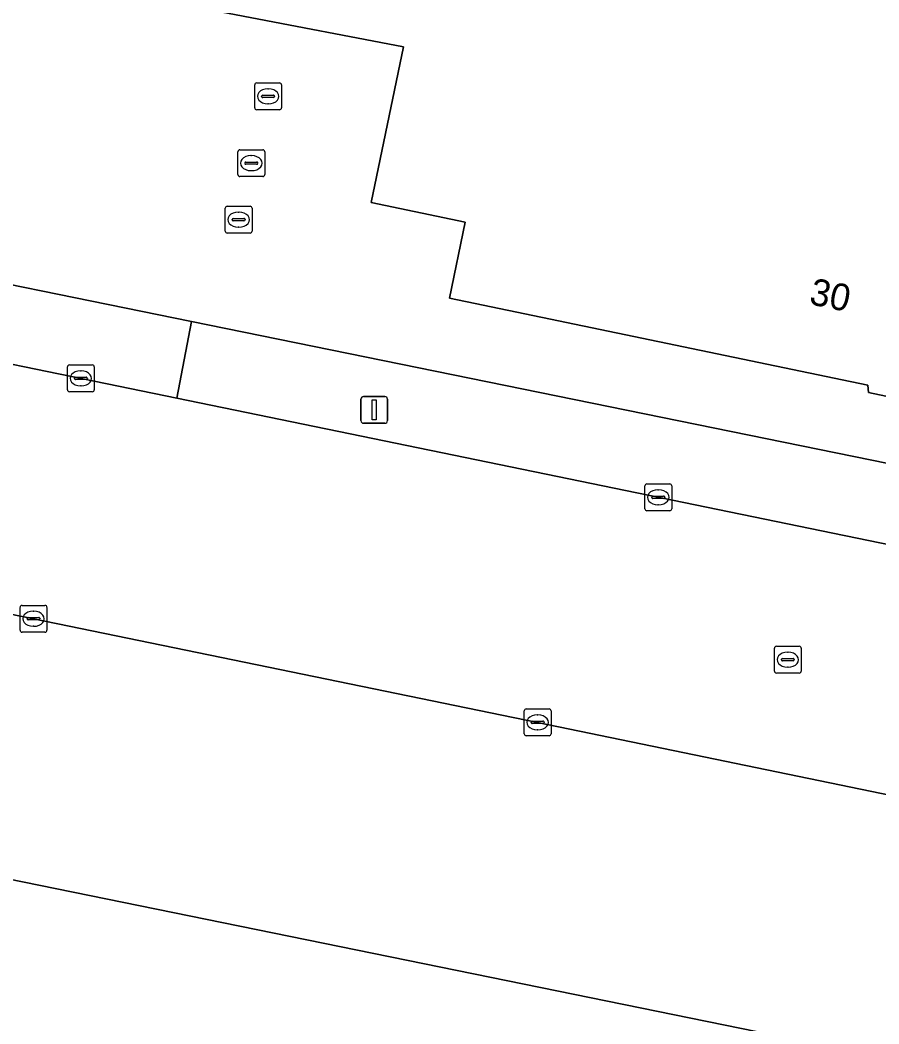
# Model space of a CAD drawing. Extents: x 157692 to 159674, y 381452 to 383291.
# Drawn here: x 158645.42 to 158677.43, y 382302.74 to 382340.17 of the extents above; entities that cross this region are included whole.
import ezdxf

# ---------------------------------------------------------------- set-up
doc = ezdxf.new("R2010")
doc.units = 0
for name, color, linetype in [('IMGEO_Erf', 7, 'Continuous'), ('IMGEO_Kolk', 7, 'Continuous'), ('IMGEO_Lichtmast', 7, 'Continuous'), ('IMGEO_Pand', 7, 'Continuous'), ('IMGEO_Pand_nummerreeks', 7, 'Continuous'), ('IMGEO_Rijbaan_lokaal_open', 7, 'Continuous'), ('IMGEO_Rioolput', 7, 'Continuous'), ('IMGEO_Voetpad_open', 7, 'Continuous')]:
    doc.layers.add(name, color=color, linetype=linetype)

msp = doc.modelspace()

# ---------------------------------------------------------------- linework, layer by layer
at = {"layer": 'IMGEO_Erf'}
for points in [[(158587.674, 382342.018), (158618.492, 382335.729), (158631.037, 382333.169), (158639.982, 382331.344), (158651.812, 382328.93), (158690.748, 382320.985), (158691.802, 382326.896), (158689.423, 382327.389), (158688.864, 382324.687), (158680.463, 382326.427), (158680.047, 382325.647), (158677.033, 382326.278), (158677.008, 382326.55), (158661.422, 382329.799), (158662.011, 382332.639), (158658.506, 382333.365), (158659.707, 382339.164), (158647.763, 382341.465)], [(158774.915, 382281.626), (158583.923, 382320.599), (158578.836, 382321.712), (158578.49, 382320.049), (158577.977, 382317.433), (158573.17, 382294.226), (158571.648, 382286.878), (158568.676, 382272.426), (158569.594, 382272.252), (158568.934, 382269.03), (158568.022, 382269.232), (158563.842, 382248.283), (158559.221, 382225.883), (158556.642, 382213.448), (158553.461, 382197.47)]]:
    msp.add_lwpolyline(points, dxfattribs=at)
at = {"layer": 'IMGEO_Kolk'}
for p, q in [((158647.182, 382326.383), (158647.182, 382327.235)), ((158647.257, 382327.309), (158648.109, 382327.309)), ((158647.67, 382327.089), (158647.695, 382327.089)), ((158648.183, 382327.235), (158648.183, 382326.383)), ((158647.441, 382326.803), (158647.441, 382326.815)), ((158647.879, 382326.766), (158647.481, 382326.766)), ((158647.484, 382326.852), (158647.882, 382326.852)), ((158647.925, 382326.815), (158647.925, 382326.803)), ((158648.109, 382326.309), (158647.257, 382326.309)), ((158647.693, 382326.529), (158647.668, 382326.529)), ((158668.704, 382321.949), (158668.704, 382322.801)), ((158668.779, 382322.875), (158669.631, 382322.875)), ((158669.192, 382322.655), (158669.217, 382322.655)), ((158669.705, 382322.801), (158669.705, 382321.949)), ((158668.963, 382322.369), (158668.963, 382322.381)), ((158669.401, 382322.332), (158669.003, 382322.332)), ((158669.006, 382322.418), (158669.404, 382322.418)), ((158669.447, 382322.381), (158669.447, 382322.369)), ((158669.631, 382321.875), (158668.779, 382321.875)), ((158669.215, 382322.095), (158669.19, 382322.095)), ((158645.418, 382317.421), (158645.418, 382318.273)), ((158645.493, 382318.347), (158646.345, 382318.347)), ((158645.906, 382318.127), (158645.931, 382318.127)), ((158646.419, 382318.273), (158646.419, 382317.421)), ((158645.677, 382317.841), (158645.677, 382317.853)), ((158646.115, 382317.804), (158645.717, 382317.804)), ((158645.72, 382317.89), (158646.118, 382317.89)), ((158646.161, 382317.853), (158646.161, 382317.841)), ((158646.345, 382317.347), (158645.493, 382317.347)), ((158645.929, 382317.567), (158645.904, 382317.567)), ((158664.206, 382313.558), (158664.206, 382314.41)), ((158664.281, 382314.484), (158665.133, 382314.484)), ((158665.207, 382314.41), (158665.207, 382313.558)), ((158664.465, 382313.978), (158664.465, 382313.99)), ((158664.903, 382313.941), (158664.505, 382313.941)), ((158664.508, 382314.027), (158664.906, 382314.027)), ((158664.694, 382314.264), (158664.719, 382314.264)), ((158664.949, 382313.99), (158664.949, 382313.978)), ((158664.717, 382313.704), (158664.692, 382313.704)), ((158665.133, 382313.484), (158664.281, 382313.484))]:
    msp.add_line(p, q, dxfattribs=at)
for points in [[(158647.182, 382326.383), (158647.182, 382327.235)], [(158647.257, 382327.309), (158648.109, 382327.309)], [(158648.183, 382327.235), (158648.183, 382326.383)], [(158648.109, 382326.309), (158647.257, 382326.309)], [(158668.704, 382321.949), (158668.704, 382322.801)], [(158668.779, 382322.875), (158669.631, 382322.875)], [(158669.705, 382322.801), (158669.705, 382321.949)], [(158669.631, 382321.875), (158668.779, 382321.875)], [(158645.418, 382317.421), (158645.418, 382318.273)], [(158645.493, 382318.347), (158646.345, 382318.347)], [(158646.419, 382318.273), (158646.419, 382317.421)], [(158646.345, 382317.347), (158645.493, 382317.347)], [(158664.206, 382313.558), (158664.206, 382314.41)], [(158664.281, 382314.484), (158665.133, 382314.484)], [(158665.207, 382314.41), (158665.207, 382313.558)], [(158665.133, 382313.484), (158664.281, 382313.484)]]:
    msp.add_lwpolyline(points, dxfattribs=at)
for centre, radius, start, end in [((158647.259, 382327.233), 0.0765, 91.552, 178.448), ((158647.259, 382327.233), 0.0765, 91.552, 178.448), ((158648.107, 382327.233), 0.0765, 1.552, 88.448), ((158648.107, 382327.233), 0.0765, 1.552, 88.448), ((158647.481, 382326.812), 0.0403, 85.8775, 175.7526), ((158647.478, 382326.802), 0.0366, 178.938, 274.7102), ((158647.882, 382326.809), 0.043, 264.8664, 352.4533), ((158647.886, 382326.814), 0.0386, 1.7309, 96.639), ((158647.259, 382326.385), 0.0765, 181.552, 268.448), ((158647.259, 382326.385), 0.0765, 181.552, 268.448), ((158648.107, 382326.385), 0.0765, 271.552, 358.448), ((158648.107, 382326.385), 0.0765, 271.552, 358.448), ((158668.781, 382322.799), 0.0765, 91.552, 178.448), ((158668.781, 382322.799), 0.0765, 91.552, 178.448), ((158669.629, 382322.799), 0.0765, 1.552, 88.448), ((158669.629, 382322.799), 0.0765, 1.552, 88.448), ((158669.003, 382322.378), 0.0403, 85.8775, 175.7526), ((158669, 382322.368), 0.0366, 178.938, 274.7102), ((158669.404, 382322.375), 0.043, 264.8664, 352.4533), ((158669.408, 382322.38), 0.0386, 1.7309, 96.639), ((158668.781, 382321.951), 0.0765, 181.552, 268.448), ((158668.781, 382321.951), 0.0765, 181.552, 268.448), ((158669.629, 382321.951), 0.0765, 271.552, 358.448), ((158669.629, 382321.951), 0.0765, 271.552, 358.448), ((158645.495, 382318.271), 0.0765, 91.552, 178.448), ((158645.495, 382318.271), 0.0765, 91.552, 178.448), ((158646.343, 382318.271), 0.0765, 1.552, 88.448), ((158646.343, 382318.271), 0.0765, 1.552, 88.448), ((158645.717, 382317.85), 0.0403, 85.8775, 175.7526), ((158645.714, 382317.84), 0.0366, 178.938, 274.7102), ((158646.118, 382317.847), 0.043, 264.8664, 352.4533), ((158646.122, 382317.852), 0.0386, 1.7309, 96.639), ((158645.495, 382317.423), 0.0765, 181.552, 268.448), ((158645.495, 382317.423), 0.0765, 181.552, 268.448), ((158646.343, 382317.423), 0.0765, 271.552, 358.448), ((158646.343, 382317.423), 0.0765, 271.552, 358.448), ((158664.283, 382314.408), 0.0765, 91.552, 178.448), ((158664.283, 382314.408), 0.0765, 91.552, 178.448), ((158665.131, 382314.408), 0.0765, 1.552, 88.448), ((158665.131, 382314.408), 0.0765, 1.552, 88.448), ((158664.505, 382313.987), 0.0403, 85.8775, 175.7526), ((158664.502, 382313.977), 0.0366, 178.938, 274.7102), ((158664.906, 382313.984), 0.043, 264.8664, 352.4533), ((158664.91, 382313.989), 0.0386, 1.7309, 96.639), ((158664.283, 382313.56), 0.0765, 181.552, 268.448), ((158664.283, 382313.56), 0.0765, 181.552, 268.448), ((158665.131, 382313.56), 0.0765, 271.552, 358.448), ((158665.131, 382313.56), 0.0765, 271.552, 358.448)]:
    msp.add_arc(centre, radius, start, end, dxfattribs=at)
for centre, major_axis, ratio, start_param, end_param in [((158647.669, 382326.809), (-0.387, 0.002), 0.722429, 4.712389, 7.853982), ((158647.694, 382326.809), (-0.39, 0.002), 0.717154, 1.570796, 4.712389), ((158669.191, 382322.375), (-0.387, 0.002), 0.722429, 4.712389, 7.853982), ((158669.216, 382322.375), (-0.39, 0.002), 0.717154, 1.570796, 4.712389), ((158645.905, 382317.847), (-0.387, 0.002), 0.722429, 4.712389, 7.853982), ((158645.93, 382317.847), (-0.39, 0.002), 0.717154, 1.570796, 4.712389), ((158664.693, 382313.984), (-0.387, 0.002), 0.722429, 4.712389, 7.853982), ((158664.718, 382313.984), (-0.39, 0.002), 0.717154, 1.570796, 4.712389)]:
    msp.add_ellipse(centre, major_axis=major_axis, ratio=ratio, start_param=start_param, end_param=end_param, dxfattribs=at)
at = {"layer": 'IMGEO_Lichtmast'}
for p, q in [((158658.122, 382325.234), (158658.122, 382326.034)), ((158658.122, 382326.034), (158658.122, 382325.234)), ((158658.222, 382326.134), (158659.012, 382326.134)), ((158659.012, 382326.134), (158658.222, 382326.134)), ((158659.112, 382326.034), (158659.112, 382325.234)), ((158659.112, 382325.234), (158659.112, 382326.034)), ((158659.012, 382325.134), (158658.222, 382325.134)), ((158658.222, 382325.134), (158659.012, 382325.134))]:
    msp.add_line(p, q, dxfattribs=at)
msp.add_lwpolyline([(158658.542, 382326.009), (158658.692, 382326.009), (158658.692, 382325.259), (158658.542, 382325.259), (158658.542, 382326.009)], dxfattribs=at)
for centre, start, end in [((158658.222, 382326.034), 90, 180), ((158658.222, 382326.034), 90, 180), ((158659.012, 382326.034), 0, 90), ((158659.012, 382326.034), 360, 90), ((158658.222, 382325.234), 180, 270), ((158658.222, 382325.234), 180, 270), ((158659.012, 382325.234), 270, 0), ((158659.012, 382325.234), 270, 0)]:
    msp.add_arc(centre, 0.1, start, end, dxfattribs=at)
at = {"layer": 'IMGEO_Pand'}
msp.add_lwpolyline([(158655.283, 382370.984), (158642.548, 382373.594), (158636.447, 382343.782), (158647.763, 382341.465), (158659.707, 382339.164), (158658.506, 382333.365), (158662.011, 382332.639), (158661.422, 382329.799), (158677.008, 382326.55), (158677.033, 382326.278), (158680.047, 382325.647), (158680.463, 382326.427), (158688.864, 382324.687), (158689.423, 382327.389), (158691.802, 382326.896), (158695.197, 382343.266), (158690.865, 382344.152), (158691.721, 382348.337), (158696.064, 382347.447), (158699.065, 382362.008)], close=True, dxfattribs=at)
at = {"layer": 'IMGEO_Rijbaan_lokaal_open'}
for points in [[(158744.89, 382306.754), (158742.717, 382307.23), (158723.644, 382311.136), (158714.521, 382313.011), (158712.813, 382313.362), (158711.707, 382313.592), (158693.337, 382317.409), (158651.257, 382326.067), (158639.414, 382328.503), (158630.487, 382330.34), (158617.947, 382332.92), (158590.277, 382338.612), (158586.837, 382339.353), (158586.676, 382339.386), (158584.918, 382330.64)], [(158585.369, 382330.295), (158606.304, 382326.032), (158627.099, 382321.705), (158645.918, 382317.846), (158664.706, 382313.983), (158683.357, 382310.127), (158703.229, 382305.989), (158720.558, 382302.454), (158740.076, 382298.433), (158761.28, 382294.05), (158776.976, 382290.837), (158783.229, 382289.567), (158794.751, 382287.205), (158799.061, 382286.324), (158819.844, 382282.089), (158838.842, 382278.204), (158844.942, 382276.94), (158852.145, 382275.448)]]:
    msp.add_lwpolyline(points, dxfattribs=at)
msp.add_lwpolyline([(158651.257, 382326.067), (158651.812, 382328.93), (158639.982, 382331.344), (158639.414, 382328.503)], close=True, dxfattribs=at)
at = {"layer": 'IMGEO_Rioolput'}
for p, q in [((158654.162, 382336.899), (158654.162, 382337.751)), ((158654.237, 382337.825), (158655.089, 382337.825)), ((158654.65, 382337.605), (158654.675, 382337.605)), ((158655.163, 382337.751), (158655.163, 382336.899)), ((158654.421, 382337.319), (158654.421, 382337.331)), ((158654.859, 382337.282), (158654.461, 382337.282)), ((158654.464, 382337.368), (158654.862, 382337.368)), ((158654.905, 382337.331), (158654.905, 382337.319)), ((158655.089, 382336.825), (158654.237, 382336.825)), ((158654.673, 382337.045), (158654.648, 382337.045)), ((158653.536, 382334.407), (158653.536, 382335.259)), ((158653.611, 382335.333), (158654.463, 382335.333)), ((158654.537, 382335.259), (158654.537, 382334.407)), ((158653.838, 382334.876), (158654.236, 382334.876)), ((158654.024, 382335.113), (158654.049, 382335.113)), ((158653.795, 382334.827), (158653.795, 382334.839)), ((158654.233, 382334.79), (158653.835, 382334.79)), ((158654.047, 382334.553), (158654.022, 382334.553)), ((158654.279, 382334.839), (158654.279, 382334.827)), ((158654.463, 382334.333), (158653.611, 382334.333)), ((158653.064, 382332.3), (158653.064, 382333.152)), ((158653.139, 382333.226), (158653.991, 382333.226)), ((158653.552, 382333.006), (158653.577, 382333.006)), ((158654.065, 382333.152), (158654.065, 382332.3)), ((158653.323, 382332.72), (158653.323, 382332.732)), ((158653.761, 382332.683), (158653.363, 382332.683)), ((158653.366, 382332.769), (158653.764, 382332.769)), ((158653.807, 382332.732), (158653.807, 382332.72)), ((158653.575, 382332.446), (158653.55, 382332.446)), ((158653.991, 382332.226), (158653.139, 382332.226)), ((158673.531, 382315.894), (158673.531, 382316.746)), ((158673.606, 382316.82), (158674.458, 382316.82)), ((158674.019, 382316.6), (158674.044, 382316.6)), ((158674.532, 382316.746), (158674.532, 382315.894)), ((158673.79, 382316.314), (158673.79, 382316.326)), ((158674.228, 382316.277), (158673.83, 382316.277)), ((158673.833, 382316.363), (158674.231, 382316.363)), ((158674.274, 382316.326), (158674.274, 382316.314)), ((158674.458, 382315.82), (158673.606, 382315.82)), ((158674.042, 382316.04), (158674.017, 382316.04))]:
    msp.add_line(p, q, dxfattribs=at)
for points in [[(158654.162, 382336.899), (158654.162, 382337.751)], [(158654.237, 382337.825), (158655.089, 382337.825)], [(158655.163, 382337.751), (158655.163, 382336.899)], [(158655.089, 382336.825), (158654.237, 382336.825)], [(158653.536, 382334.407), (158653.536, 382335.259)], [(158653.611, 382335.333), (158654.463, 382335.333)], [(158654.537, 382335.259), (158654.537, 382334.407)], [(158654.463, 382334.333), (158653.611, 382334.333)], [(158653.064, 382332.3), (158653.064, 382333.152)], [(158653.139, 382333.226), (158653.991, 382333.226)], [(158654.065, 382333.152), (158654.065, 382332.3)], [(158653.991, 382332.226), (158653.139, 382332.226)], [(158673.531, 382315.894), (158673.531, 382316.746)], [(158673.606, 382316.82), (158674.458, 382316.82)], [(158674.532, 382316.746), (158674.532, 382315.894)], [(158674.458, 382315.82), (158673.606, 382315.82)]]:
    msp.add_lwpolyline(points, dxfattribs=at)
for centre, radius, start, end in [((158654.239, 382337.749), 0.0765, 91.552, 178.448), ((158654.239, 382337.749), 0.0765, 91.552, 178.448), ((158655.087, 382337.749), 0.0765, 1.552, 88.448), ((158655.087, 382337.749), 0.0765, 1.552, 88.448), ((158654.461, 382337.328), 0.0403, 85.8775, 175.7526), ((158654.458, 382337.318), 0.0366, 178.938, 274.7102), ((158654.862, 382337.325), 0.043, 264.8664, 352.4533), ((158654.866, 382337.33), 0.0386, 1.7309, 96.639), ((158654.239, 382336.901), 0.0765, 181.552, 268.448), ((158654.239, 382336.901), 0.0765, 181.552, 268.448), ((158655.087, 382336.901), 0.0765, 271.552, 358.448), ((158655.087, 382336.901), 0.0765, 271.552, 358.448), ((158653.613, 382335.257), 0.0765, 91.552, 178.448), ((158653.613, 382335.257), 0.0765, 91.552, 178.448), ((158654.461, 382335.257), 0.0765, 1.552, 88.448), ((158654.461, 382335.257), 0.0765, 1.552, 88.448), ((158653.835, 382334.836), 0.0403, 85.8775, 175.7526), ((158654.24, 382334.838), 0.0386, 1.7309, 96.639), ((158653.832, 382334.826), 0.0366, 178.938, 274.7102), ((158654.236, 382334.833), 0.043, 264.8664, 352.4533), ((158653.613, 382334.409), 0.0765, 181.552, 268.448), ((158653.613, 382334.409), 0.0765, 181.552, 268.448), ((158654.461, 382334.409), 0.0765, 271.552, 358.448), ((158654.461, 382334.409), 0.0765, 271.552, 358.448), ((158653.141, 382333.15), 0.0765, 91.552, 178.448), ((158653.141, 382333.15), 0.0765, 91.552, 178.448), ((158653.989, 382333.15), 0.0765, 1.552, 88.448), ((158653.989, 382333.15), 0.0765, 1.552, 88.448), ((158653.363, 382332.729), 0.0403, 85.8775, 175.7526), ((158653.36, 382332.719), 0.0366, 178.938, 274.7102), ((158653.764, 382332.726), 0.043, 264.8664, 352.4533), ((158653.768, 382332.731), 0.0386, 1.7309, 96.639), ((158653.141, 382332.302), 0.0765, 181.552, 268.448), ((158653.141, 382332.302), 0.0765, 181.552, 268.448), ((158653.989, 382332.302), 0.0765, 271.552, 358.448), ((158653.989, 382332.302), 0.0765, 271.552, 358.448), ((158673.608, 382316.744), 0.0765, 91.552, 178.448), ((158673.608, 382316.744), 0.0765, 91.552, 178.448), ((158674.456, 382316.744), 0.0765, 1.552, 88.448), ((158674.456, 382316.744), 0.0765, 1.552, 88.448), ((158673.83, 382316.323), 0.0403, 85.8775, 175.7526), ((158673.827, 382316.313), 0.0366, 178.938, 274.7102), ((158674.231, 382316.32), 0.043, 264.8664, 352.4533), ((158674.235, 382316.325), 0.0386, 1.7309, 96.639), ((158673.608, 382315.896), 0.0765, 181.552, 268.448), ((158673.608, 382315.896), 0.0765, 181.552, 268.448), ((158674.456, 382315.896), 0.0765, 271.552, 358.448), ((158674.456, 382315.896), 0.0765, 271.552, 358.448)]:
    msp.add_arc(centre, radius, start, end, dxfattribs=at)
for centre, major_axis, ratio, start_param, end_param in [((158654.649, 382337.325), (-0.387, 0.002), 0.722429, 4.712389, 7.853982), ((158654.674, 382337.325), (-0.39, 0.002), 0.717154, 1.570796, 4.712389), ((158654.023, 382334.833), (-0.387, 0.002), 0.722429, 4.712389, 7.853982), ((158654.048, 382334.833), (-0.39, 0.002), 0.717154, 1.570796, 4.712389), ((158653.551, 382332.726), (-0.387, 0.002), 0.722429, 4.712389, 7.853982), ((158653.576, 382332.726), (-0.39, 0.002), 0.717154, 1.570796, 4.712389), ((158674.018, 382316.32), (-0.387, 0.002), 0.722429, 4.712389, 7.853982), ((158674.043, 382316.32), (-0.39, 0.002), 0.717154, 1.570796, 4.712389)]:
    msp.add_ellipse(centre, major_axis=major_axis, ratio=ratio, start_param=start_param, end_param=end_param, dxfattribs=at)
at = {"layer": 'IMGEO_Voetpad_open'}
for points in [[(158776.976, 382290.837), (158761.28, 382294.05), (158740.076, 382298.433), (158720.558, 382302.454), (158703.229, 382305.989), (158683.357, 382310.127), (158664.706, 382313.983), (158645.918, 382317.846), (158627.099, 382321.705), (158606.304, 382326.032), (158585.369, 382330.295)], [(158693.858, 382320.35), (158691.021, 382320.929), (158690.748, 382320.985), (158651.812, 382328.93), (158651.257, 382326.067), (158693.337, 382317.409)], [(158585.636, 382328.823), (158583.923, 382320.599), (158774.915, 382281.626), (158775.174, 382281.573), (158776.28, 382289.179), (158776.115, 382289.213), (158776.367, 382290.437)]]:
    msp.add_lwpolyline(points, dxfattribs=at)

# ---------------------------------------------------------------- texts
at = {"layer": 'IMGEO_Pand_nummerreeks'}
msp.add_text('30', height=1, rotation=348.225, dxfattribs=at).set_placement((158674.79, 382329.586))

doc.saveas('drawing.dxf')
